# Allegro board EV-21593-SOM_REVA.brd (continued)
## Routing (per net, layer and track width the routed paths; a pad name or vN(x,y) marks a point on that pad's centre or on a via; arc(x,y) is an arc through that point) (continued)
N13: length 63.3
  TOP w0.14: v2(15.88,34.92) U7.2
  TOP w0.203: U1.P2 v1(25.82,50.14)
  L4_SIG w0.14: v1(15.62,47.37) 16.13,47.88 16.99,47.88 18.05,48.94 19.73,48.94 20.57,49.78 23.42,49.78 23.46,49.74 25.42,49.74 v1(25.82,50.14)
  L5_SIG w0.14: v2(15.88,34.92) 15.37,34.42 15.37,18.41 16.38,17.4 16.38,13.97 18.41,11.94 18.41,9.4 19.18,8.64 19.18,2.79 v1(18.03,1.65)
  BOTTOM w0.14: v1(18.03,1.65) 17.83,2.03 J2.7 ; v2(15.88,34.92) 14.86,35.94 14.86,46.61 v1(15.62,47.37)
PA_00/SPI2_MISO/OSPI_MISO/SMC0_D00: length 63.8
  TOP w0.203: v1(26.62,50.94) U1.N3
  L4_SIG w0.14: v1(24.89,9.14) 24.26,8.51 24.26,7.37 23.75,6.86 20.07,6.86 19.43,6.22 19.43,5.46 18.86,4.89 16.57,4.89 v1(16.13,4.45)
  L5_SIG w0.14: v1(24.89,9.14) 24.89,16 23.49,17.4 23.49,19.81 22.86,20.45 22.86,29.21 22.23,29.84 v2(22.23,33.02) 20.62,34.63 20.62,41.54 21.02,41.94 21.82,41.94 22.22,42.34 22.22,43.81 22.48,44.07 22.48,49.53 22.86,49.91 23.49,49.91 23.88,50.29 24.31,50.29 24.56,50.54 26.22,50.54 v1(26.62,50.94)
  BOTTOM w0.14: J2.3 16.56,4.06 v1(16.13,4.45) ; R72.2 23.49,32.38 22.86,32.38 v2(22.23,33.02)
PA_01/SPI2_MOSI/OSPI_MOSI/SMC0_D01: length 70.7
  TOP w0.14: U2.15 29.1,38.69 29.06,38.73 27.24,38.73 24.64,41.34 22.22,41.34 v1(21.82,40.94)
  TOP w0.203: U1.P3 v1(26.62,50.14)
  L4_SIG w0.14: v1(25.78,9.14) 25.02,8.38 25.02,7.24 24.13,6.35 20.32,6.35 19.81,5.84 19.81,4.32 v1(17.15,1.65)
  L5_SIG w0.14: v1(25.78,9.14) 25.78,16.51 24.51,17.78 24.51,20.19 23.37,21.34 23.37,29.47 22.87,29.97 22.87,33.66 22.48,34.04 21.98,34.04 21.22,34.8 21.22,40.34 v1(21.82,40.94) 23.02,42.14 23.02,44.36 23.42,44.76 23.42,49.23 23.93,49.74 26.22,49.74 v1(26.62,50.14)
  BOTTOM w0.14: v1(17.15,1.65) 17.19,2.16 J2.5
PA_03/SPI2_D3/OSPI_D3/TWI3_SDA/SMC0_D03: length 59.7
  TOP w0.14: v2(15.88,38.73) U8.2
  TOP w0.203: U1.R3 v1(26.62,49.34)
  L4_SIG w0.14: v1(26.62,49.34) 26.22,48.94 23.69,48.94 23.27,48.51 18.29,48.51 v1(17.15,47.37)
  L5_SIG w0.14: v1(17.15,47.37) 16.76,46.99 16.76,39.62 v2(15.88,38.73) 14.99,37.85 14.99,13.46 17.15,11.3 17.15,9.02 17.53,8.64 18.41,8.64 18.67,8.38 18.67,7.24 18.16,6.73 18.16,4.95 v1(18.67,4.45)
  BOTTOM w0.14: J2.9 18.46,4.06 v1(18.67,4.45)
PA_04/SPI2_CLK/OSPI_CLK/SMC0_D04: length 69.5
  TOP w0.14: v1(23.42,40.94) 24.82,39.54 24.82,38.68 v2(26.03,37.46)
  TOP w0.203: U1.R1 v1(25.02,49.34)
  L5_SIG w0.14: v1(19.05,1.65) 19.56,1.14 32.13,1.14 32.64,1.65 32.64,8.51 29.72,11.43 29.72,17.78 28.45,19.05 28.45,22.48 27.3,23.62 27.3,35.69 26.03,36.96 v2(26.03,37.46) ; v1(23.42,40.94) 23.42,44.12 23.82,44.52 23.82,48.96 24.2,49.34 v1(25.02,49.34)
  BOTTOM w0.14: J2.11 19.1,2.03 v1(19.05,1.65) ; R73.1 v2(26.03,37.46)
PA_05/SPI2_SEL1B/OSPI_SEL1B/SMC0_D05/SPI2_SSB: length 62.3
  TOP w0.14: U6.2 v2(15.88,31.12)
  TOP w0.203: v1(25.82,48.54) U1.T2
  L4_SIG w0.14: v1(15.62,46.61) 18.16,46.61 19.43,47.88 19.94,47.88 20.57,47.24 23.39,47.24 24.29,48.14 25.42,48.14 v1(25.82,48.54)
  L5_SIG w0.14: v2(15.88,31.12) 15.88,21.59 18.92,18.54 18.92,11.05 19.69,10.29 19.69,4.06 19.94,3.81 v1(19.94,1.65)
  BOTTOM w0.14: J2.13 19.73,2.16 v1(19.94,1.65) ; v2(15.88,31.12) 16.51,31.75 16.51,35.81 15.24,37.08 15.24,46.23 v1(15.62,46.61)
PA_10/TWI0_SCL/SPI1_CLK/TM0_TMR0/SMC0_D10: length 64.7
  TOP w0.203: v1(25.82,47.74) U1.U2
  L5_SIG w0.14: v1(25.82,47.74) 25.42,48.14 24.82,48.14 24.22,47.54 24.22,44.14 23.82,43.74 23.82,40.74 24.13,40.43 24.13,29.97 23.88,29.72 23.88,23.62 24.26,23.24 25.27,23.24 25.65,22.86 25.65,17.53 26.29,16.89 26.29,9.78 26.8,9.27 26.8,3.18 v1(25.27,1.65) 24.51,2.41 21.59,2.41 20.83,3.18 20.83,6.35 20.19,6.99 v1(20.19,8.13)
  BOTTOM w0.14: v1(25.27,1.65) 25.45,2.03 J2.31 ; v1(20.19,8.13) 19.73,7.62 J2.14
PA_12/FLG0/SPI1_MOSI/TM0_TMR1/SMC0_D12: length 68.2
  TOP w0.203: v1(29.02,46.14) U1.W6
  L4_SIG w0.14: v1(21.34,5.33) 21.84,5.84 22.35,5.84 22.61,5.59 22.61,4.06 23.24,3.43 26.16,3.43 26.67,2.92 30.1,2.92 30.48,2.54 34.67,2.54 v1(35.56,1.65)
  L5_SIG w0.14: v1(35.56,1.65) 35.56,2.92 35.43,3.05 35.43,5.84 34.8,6.48 34.8,11.18 35.31,11.68 35.31,12.32 33.91,13.72 33.91,17.15 34.67,17.91 34.67,18.67 34.04,19.3 34.04,20.95 34.67,21.59 34.67,24.64 29.97,29.34 29.97,37.78 28.96,38.8 28.96,42.54 28.62,42.88 28.62,45.74 v1(29.02,46.14)
  BOTTOM w0.14: v1(21.34,5.33) 21.34,5.38 21,5.71 J2.18
PA_15/TWI2_SDA/SPI1_D3/UART1_TXB/SMC0_D15: length 68.1
  TOP w0.14: R69.1 v1(35.42,40.14)
  TOP w0.203: v1(30.62,46.14) U1.W8
  L4_SIG w0.14: v1(30.62,46.14) 31.02,45.74 31.02,42.94 32.62,41.34 34.22,41.34 v1(35.42,40.14) ; v1(25.4,4.45) 25.91,3.94 26.92,3.94 27.43,3.43 30.61,3.43 31.12,2.92 38.23,2.92 v1(39.5,1.65)
  L5_SIG w0.14: v1(39.5,1.65) 39.5,4.57 39.81,4.89 39.81,7.3 38.99,8.13 38.99,27.69 36.7,29.97 36.7,37.33 35.42,38.61 v1(35.42,40.14)
  BOTTOM w0.14: v1(25.4,4.45) 25.45,4.83 J2.32
PB_02/MLB0_CLK/FLG3/LP1_ACK/SMC0_AWEB/TM0_ACLK4: length 128.5
  TOP w0.14: v1(11.43,43.69) 11.43,43.05 11.94,42.55 14.99,42.55 16.38,43.94 48.64,43.94 v1(50.8,41.78)
  TOP w0.203: v1(30.62,60.54) U1.B8
  L4_SIG w0.14: v2(11.3,57.4) 16.89,57.4 17.62,58.13 17.62,59.44 20.32,62.14 29.62,62.14 30.22,61.54 30.22,60.94 v1(30.62,60.54)
  L5_SIG w0.14: v2(50.67,7.37) 50.67,10.29 51.94,11.56 51.94,24 51.31,24.64 51.31,30.35 50.42,31.24 50.42,41.4 v1(50.8,41.78)
  BOTTOM w0.14: v1(50.8,41.78) 51.69,40.89 53.47,40.89 55.24,42.67 J1.96 ; J2.98 46.4,7.67 46.61,7.87 50.16,7.87 v2(50.67,7.37) ; v1(11.43,43.69) 12.83,45.09 12.83,55.88 v2(11.3,57.4)
PB_06/LP0_CLK/SPI1_SEL5B/TRACE0_CLK: length 70.9
  TOP w0.203: v1(28.22,46.94) U1.V5
  L4_SIG w0.14: v1(46.74,1.65) 45.09,3.3 32,3.3 31.37,3.94 28.32,3.94 v1(27.81,4.45)
  L5_SIG w0.14: v1(27.81,4.45) 27.18,5.08 27.18,5.97 27.43,6.22 27.43,18.03 26.42,19.05 26.42,22.86 25.53,23.75 25.53,29.34 24.64,30.23 24.64,32.1 25.4,32.86 25.4,35.56 24.89,36.07 24.89,44.57 24.62,44.84 24.62,47.14 24.82,47.34 27.82,47.34 v1(28.22,46.94)
  BOTTOM w0.14: v1(46.74,1.65) 47.04,2.16 J2.99
PB_07/LP0_D0/SPI2_SEL5B/TRACE0_D00: length 62.3
  TOP w0.14: v1(45.72,1.65) 44.83,2.54 34.92,2.54 v1(34.04,1.65)
  TOP w0.203: v1(27.42,46.14) U1.W4
  L5_SIG w0.14: v1(27.42,46.14) 27.02,45.74 27.02,43.81 26.67,43.46 26.67,38.99 28.45,37.21 28.45,23.75 29.4,22.8 29.4,22.23 32.13,19.49 32.13,10.79 33.4,9.53 33.4,4.06 34.04,3.43 v1(34.04,1.65)
  BOTTOM w0.14: J2.95 45.77,2.03 v1(45.72,1.65)
PB_08/LP0_D1/SPI1_SEL7B/TM0_TMR6/TRACE0_D01: length 61.4
  TOP w0.203: v1(26.62,46.14) U1.W3
  L4_SIG w0.14: v1(32.13,4.45) 33.02,3.56 44.7,3.56 v1(45.59,4.45)
  L5_SIG w0.14: v1(26.62,46.14) 26.22,45.74 26.22,44.74 25.27,43.79 25.27,37.08 26.67,35.69 26.67,23.37 27.43,22.61 27.43,19.05 28.57,17.91 28.57,11.43 31.75,8.26 31.75,4.83 v1(32.13,4.45)
  BOTTOM w0.14: J2.93 45.13,4.06 v1(45.59,4.45)
PB_09/LP0_D2/SPI2_SEL7B/TM0_TMR7/TRACE0_D02: length 59
  TOP w0.14: v1(44.83,1.65) 44.32,1.14 37.72,1.14 v1(37.21,1.65)
  TOP w0.203: v1(29.02,46.94) U1.V6
  L5_SIG w0.14: v1(37.21,1.65) 36.45,2.41 36.45,12.57 35.31,13.72 35.31,17.4 35.43,17.53 35.43,25.4 32.13,28.7 32.13,32.64 31.62,33.15 31.62,37.57 29.82,39.37 29.82,44.54 29.42,44.94 29.42,46.54 v1(29.02,46.94)
  BOTTOM w0.14: v1(44.83,1.65) 44.5,2.03 J2.91
PB_10/LP0_D3/SPI1_SEL2B/TRACE0_D03: length 74.5
  TOP w0.203: v1(26.62,45.34) U1.Y3
  L4_SIG w0.14: v1(22.1,5.33) 22.1,3.94 23.11,2.92 25.65,2.92 26.42,2.16 32.64,2.16 v1(33.15,1.65) 33.66,1.14 42.8,1.14 v1(43.31,1.65)
  L5_SIG w0.14: v1(33.15,1.65) 33.15,2.79 33.02,2.92 33.02,9.02 30.99,11.05 30.99,17.53 31.24,17.78 31.24,19.43 28.96,21.72 28.96,22.61 27.94,23.62 27.94,35.69 26.67,36.96 26.67,37.99 26.31,38.35 26.31,43.89 26.62,44.2 v1(26.62,45.34)
  BOTTOM w0.14: J2.22 22.27,5.71 v1(22.1,5.33) ; v1(43.31,1.65) 43.86,2.16 J2.89
PB_11/LP0_D4/SPI0_RDY/UART2_RXB/TM0_ACI2: length 70.1
  TOP w0.14: v1(23.49,7.87) 23.88,7.49 27.69,7.49 v1(28.32,8.13)
  TOP w0.203: U1.Y4 v1(27.42,45.34)
  L4_SIG w0.14: v1(28.57,5.33) 29.02,4.89 33.46,4.89 v1(33.91,4.45) 34.42,3.94 42.29,3.94 v1(42.8,4.45)
  L5_SIG w0.14: v1(33.91,4.45) 33.91,10.92 33.15,11.68 33.15,19.81 31.62,21.34 31.62,25.65 28.96,28.32 28.96,37.46 27.94,38.48 27.94,43.82 27.42,44.34 v1(27.42,45.34)
  BOTTOM w0.14: v1(23.49,7.87) 23.54,7.83 J2.26 ; J2.87 43.23,4.06 v1(42.8,4.45) ; v1(28.57,5.33) 28.62,5.71 J2.42 28.62,7.83 v1(28.32,8.13)
PB_12/LP0_D5/SPI2_SEL3B/UART2_TXB: length 66.9
  TOP w0.203: v1(29.82,46.94) U1.V7
  L4_SIG w0.14: v1(27.81,5.33) 28.32,5.84 33.4,5.84 34.35,4.89 36.51,4.89 v1(36.96,4.45)
  L5_SIG w0.14: v1(29.82,46.94) 30.22,46.54 30.22,39.62 30.23,39.62 31.88,37.97 31.88,33.78 32.64,33.02 32.64,29.21 35.81,26.03 35.81,17.53 36.32,17.02 36.32,13.33 36.83,12.83 36.83,6.86 37.46,6.22 37.46,4.95 v1(36.96,4.45) 38.61,2.79 38.61,1.65 39.12,1.14 41.91,1.14 v1(42.42,1.65)
  BOTTOM w0.14: J2.40 27.99,5.71 v1(27.81,5.33) ; v1(42.42,1.65) 42.59,2.03 J2.85
PB_13/SPI2_DQS/LP0_D6/SPI1_SEL3B/UART2_RTSB: length 75.3
  TOP w0.14: v1(34.8,1.65) 35.31,2.16 41.27,2.16 v1(41.78,1.65)
  TOP w0.203: v1(28.22,46.14) U1.W5
  L4_SIG w0.14: v1(29.21,8.13) 28.19,7.11 26.67,7.11 25.4,5.84 24.38,5.84 v1(23.88,5.33)
  L5_SIG w0.14: v1(34.8,1.65) v1(34.8,4.45) 34.29,4.95 34.29,11.3 33.53,12.06 33.53,17.27 34.29,18.03 34.29,18.54 33.66,19.18 33.66,20.07 32.64,21.08 32.64,25.53 29.46,28.7 29.46,37.64 28.32,38.78 28.32,44.33 27.82,44.83 27.82,45.74 v1(28.22,46.14)
  BOTTOM w0.14: J2.83 41.96,2.03 v1(41.78,1.65) ; v1(29.21,8.13) 29.21,6.69 J2.44 29.26,5.16 29.53,4.89 34.35,4.89 v1(34.8,4.45) ; J2.27 24.18,4.19 23.88,4.49 v1(23.88,5.33)
PB_14/LP0_D7/SPI0_SEL3B/UART2_CTSB: length 64.2
  TOP w0.203: v1(36.22,45.34) U1.Y14
  L5_SIG w0.14: v1(41.02,1.65) 41.02,3.49 41.08,3.56 41.08,6.22 41.02,6.29 41.02,27.18 37.46,30.73 37.46,39.03 36.62,39.88 36.62,41.94 36.22,42.34 v1(36.22,45.34) ; v1(29.72,5.33) 29.72,3.68 30.35,3.05 v1(30.35,1.65)
  BOTTOM w0.14: J2.46 29.89,5.84 v1(29.72,5.33) ; v1(30.35,1.65) 30.86,1.14 40.51,1.14 v1(41.02,1.65) 41.32,2.16 J2.81
PB_15/LP1_D0/SPI0_SEL4B/SMC0_ADDR4: length 51.6
  TOP w0.14: v1(40,4.45) 40.45,4.89 45.15,4.89 v1(45.59,5.33)
  TOP w0.203: v1(36.22,46.14) U1.W14
  L5_SIG w0.14: v1(36.22,46.14) 35.82,45.74 35.82,38.99 37.08,37.73 37.08,30.48 40,27.56 40,7.75 40.13,7.62 40.13,4.7 v1(40,4.45)
  BOTTOM w0.14: J2.96 45.77,5.71 v1(45.59,5.33)
PC_00/LP1_D1/TWI4_SCL/TRACE0_D04/SPI1_SEL4B: length 53.1
  TOP w0.203: v1(35.42,46.94) U1.V13
  L4_SIG w0.14: v1(38.99,4.45) 39.43,4.89 44.45,4.89 v1(44.83,5.33)
  L5_SIG w0.14: v1(38.99,4.45) 39.5,4.95 39.5,6.99 38.61,7.87 38.61,26.8 35.18,30.23 35.18,36.83 34.92,37.08 34.92,43.97 35.02,44.07 35.02,46.54 v1(35.42,46.94)
  BOTTOM w0.14: v1(44.83,5.33) 45.13,5.71 J2.94
PC_01/LP1_D2/TWI4_SDA/TRACE0_D05/SPI2_SEL4B: length 51.7
  TOP w0.203: v1(37.02,46.14) U1.W15
  L5_SIG w0.14: v1(44.83,4.45) 43.94,3.56 41.97,3.56 41.47,4.06 41.47,6.35 42.04,6.92 42.04,20.07 41.4,20.7 41.4,27.5 37.85,31.05 37.85,39.58 37.42,40 37.42,41.54 36.62,42.34 36.62,45.74 v1(37.02,46.14)
  BOTTOM w0.14: v1(44.83,4.45) 44.32,4.95 44.32,5.46 44.5,5.71 J2.92
PC_02/LP1_D3/TWI5_SCL/TRACE0_D06/SPI1_SEL6B: length 46.9
  TOP w0.203: v1(37.02,45.34) U1.Y15
  L5_SIG w0.14: v1(37.02,45.34) 37.02,44.34 37.82,43.54 37.82,40.26 38.23,39.85 38.23,31.35 38.6,30.98 41.15,28.45 41.78,27.81 41.78,21.15 42.35,20.57 42.35,5.08 42.55,4.89 43.18,4.89 v1(43.56,4.45)
  BOTTOM w0.14: v1(43.56,4.45) 43.86,4.83 J2.90
PC_03/LP1_D4/TWI5_SDA/TRACE0_D07/SPI2_SEL6B: length 45.4
  TOP w0.203: v1(37.82,46.14) U1.W16
  L5_SIG w0.14: v1(43.43,5.33) 43.43,6.1 42.67,6.86 42.67,20.83 42.16,21.34 42.16,27.94 38.6,31.5 38.6,40.13 38.22,40.51 38.22,43.54 37.42,44.34 37.42,45.74 v1(37.82,46.14)
  BOTTOM w0.14: J2.88 43.23,5.71 v1(43.43,5.33)
PC_04/LP1_D5/OSPI_SEL2B/SMC0_ADDR5: length 49.2
  TOP w0.203: v1(38.62,45.34) U1.Y17
  L4_SIG w0.14: v1(42.8,5.33) 43.31,5.84 45.85,5.84 v1(46.35,5.33)
  L5_SIG w0.14: v1(38.62,45.34) 39.42,44.54 39.42,31.62 43.18,27.86 43.18,25.53 43.81,24.89 43.81,14.48 44.07,14.22 44.07,7.62 v1(46.35,5.33)
  BOTTOM w0.14: v1(42.8,5.33) 42.59,5.71 J2.86
PC_05/LP1_D6/OSPI_SEL3B/TM0_TMR8/SMC0_ADDR6: length 51.3
  TOP w0.203: v1(36.22,46.94) U1.V14
  L4_SIG w0.14: v1(41.91,5.33) 41.4,5.84 39.5,5.84 v1(38.99,5.33)
  L5_SIG w0.14: v1(38.99,5.33) 38.99,6.86 38.23,7.62 38.23,26.29 34.67,29.84 34.67,42.35 34.22,42.8 34.22,47.14 34.42,47.34 U1.V14 v1(36.22,46.94)
  BOTTOM w0.14: J2.84 41.96,5.71 v1(41.91,5.33)
PC_06/LP1_D7/SPI1_RDY/SMC0_ADDR7: length 49.9
  TOP w0.203: v1(38.62,46.14) U1.W17
  L5_SIG w0.14: v1(42.04,4.45) 42.55,3.94 43.69,3.94 44.07,4.32 44.07,6.22 43.05,7.24 43.05,21.08 42.55,21.59 42.55,28.07 41.66,28.96 39.02,31.62 39.02,43.94 38.22,44.74 38.22,45.74 v1(38.62,46.14)
  BOTTOM w0.14: v1(42.04,4.45) 42.04,4.49 41.32,5.21 J2.82
PC_07/LP1_CLK/OSPI_SEL4B/TM0_TMR9/SYS_FAULT: length 46.1
  TOP w0.203: v1(39.42,45.34) U1.Y18
  L5_SIG w0.14: v1(47.37,5.33) 44.45,8.26 44.45,21.84 45.09,22.48 45.09,24.64 44.7,25.02 44.32,25.02 43.56,25.78 43.56,28.04 43.55,28.05 39.82,31.75 39.82,44.94 v1(39.42,45.34)
  BOTTOM w0.14: J2.100 47.04,5.71 v1(47.37,5.33)
PG1: length 34.5
  TOP w0.254: v2(47.12,14.22) 46.71,14.45 46.48,14.67 U14.2 ; U15.1 19.31,13.99 19.56,13.74 19.56,13.08 19.81,12.83 20.7,12.83 R56.2
  TOP w0.305: R56.2 v2(20.83,12.06)
  L4_SIG w0.305: v2(47.12,14.22) 47.12,12.95 46.35,12.19 44.07,12.19 42.42,10.54 34.42,10.54 33.53,9.65 29.97,9.65 27.56,12.06 v2(20.83,12.06)
PG3: length 15.3
  TOP w0.254: U5.1 33.66,15.64 33.66,14.99 33.91,14.73 v2(34.8,14.73) ; v2(43.56,13.46) 44.58,13.46 44.84,13.72 U14.11
  TOP w0.305: R62.1 42.93,13.21 43.18,13.46 v2(43.56,13.46)
  L4_SIG w0.305: v2(43.56,13.46) 43.56,14.48 42.93,15.11 36.45,15.11 36.07,14.73 v2(34.8,14.73)
PG4: length 2.2
  TOP w0.254: U5.14 30.1,15.64 29.46,14.99 R61.1
RXD: length 15
  TOP w0.14: v2(20.19,74.8) 19.3,75.14 U11.8 ; v2(19.81,85.47) 19.43,85.11 U10.2
  L4_SIG w0.14: v2(19.81,85.47) 19.18,84.84 19.18,75.82 v2(20.19,74.8)
SPIFLASH_SPI2D2: length 17.1
  TOP w0.14: U2.9 29.09,31.09 26.64,31.09 v2(26.03,30.48) ; v2(15.88,33.53) 16.62,34.28 U7.4
  L4_SIG w0.14: v2(26.03,30.48) 25.4,31.12 20.83,31.12 18.41,33.53 v2(15.88,33.53)
  BOTTOM w0.14: R79.2 v2(26.03,30.48)
SPIFLASH_SPI2D3: length 9.4
  TOP w0.14: v2(23.49,40) 22.86,39.37 21.72,39.37 21.08,40 U2.1 19.05,40 18.8,39.75 18.8,38.99 18.54,38.73 17.4,38.73 17.27,38.61 17.27,38.09 U8.4
  BOTTOM w0.14: v2(23.49,40) R78.2
SYS_BMODE0: length 45.3
  TOP w0.14: v2(8.26,80.9) SW1.1
  TOP w0.203: U1.B10 v1(32.22,60.54)
  L4_SIG w0.14: v2(8.26,80.9) 8.26,70.74 9.14,69.85 18.54,69.85 20.32,68.07 30.1,68.07 30.86,67.31 30.86,63.75 32.22,62.4 v1(32.22,60.54)
  BOTTOM w0.14: v2(8.26,80.9) 8.26,79.69 R20.1
SYS_BMODE1: length 59.4
  TOP w0.14: v2(3.05,68.96) 3.05,67.03 SW1.2
  TOP w0.203: v1(31.42,60.54) U1.B9
  L4_SIG w0.14: v1(31.42,60.54) 31.42,62.18 29.84,63.75 29.84,66.8 29.08,67.56 20.07,67.56 18.29,69.34 7.11,69.34 5.97,70.48 5.97,77.72 6.99,78.74 v2(6.99,80.9)
  BOTTOM w0.14: v2(3.05,68.96) 3.05,69.85 R21.1 3.02,74.45 5.05,76.48 5.05,78.97 v2(6.99,80.9)
SYS_BMODE2: length 47.1
  TOP w0.14: v2(3.18,80.9) SW1.4
  TOP w0.203: U1.A8 v1(30.62,61.34)
  L4_SIG w0.14: v2(3.18,80.9) 3.94,80.14 3.94,70.1 5.21,68.83 18.03,68.83 19.81,67.06 28.03,67.06 28.79,66.29 28.79,63.79 30.62,61.96 v1(30.62,61.34)
  BOTTOM w0.14: v2(3.18,80.9) 3.18,79.69 R22.1
SYS_CLKIN0: length 38
  TOP w0.14: v2(44.45,39.37) 44.45,39.19 44.48,38.58 R23.2 ; R33.2 20.19,52.07 20.45,52.32 23.17,52.32 23.75,51.74 v1(25.02,51.74)
  TOP w0.203: U1.N1 v1(25.02,51.74)
  L5_SIG w0.14: v1(25.02,51.74) U1.N1 43.05,51.34 44.45,49.94 v2(44.45,39.37)
SYS_CLKOUT: length 44
  TOP w0.203: v1(26.62,51.74) U1.M3
  L4_SIG w0.14: v1(26.62,51.74) 26.22,52.14 23.62,52.14 23.42,52.34 6.49,52.34 v2(6.48,52.32)
  L5_SIG w0.14: v2(6.48,52.32) 6.48,48.89 3.68,46.1 3.68,34.29 v1(5.46,32.51)
  BOTTOM w0.14: v1(5.46,32.51) J3.38
SYS_XTAL0: length 6.3
  TOP w0.14: U1.L1 24.38,52.94 23.73,53.59 20.32,53.59 20.07,53.34 R32.1
TWI2_SCL: length 179.1
  TOP w0.14: v1(48.89,3.43) 32.51,3.43 31.62,2.54 28.7,2.54 v1(27.81,1.65) ; v2(44.32,88.9) R112.2 ; v2(46.99,30.48) 46.35,31.37 46.33,31.38 U9.12 ; U16.8 16.81,65.79 17.19,66.17 17.4,66.17 v2(18.29,67.06) ; v1(33.82,37.34) R70.2
  L4_SIG w0.14: v1(33.82,37.34) 28.57,37.34 27.94,36.7 12.95,36.7 12.7,36.96 12.7,37.72 v2(12.06,38.35)
  L5_SIG w0.14: v2(44.32,88.9) 43.31,89.92 40.77,89.92 39.88,89.03 29.59,89.03 28.19,87.63 22.23,87.63 21.34,86.74 21.34,73.91 18.29,70.87 v2(18.29,67.06) ; v2(46.99,30.48) 46.99,27.43 51.18,23.24 51.18,12.57 48.89,10.29 v1(48.89,3.43)
  BOTTOM w0.14: v2(12.06,38.35) 12.57,37.85 13.72,37.85 14.48,38.61 14.48,53.98 13.84,54.61 13.84,59.05 15.62,60.83 15.62,65.15 16.26,65.79 17.02,65.79 v2(18.29,67.06) ; R70.2 v1(33.82,37.34) 41.44,29.72 46.23,29.72 v2(46.99,30.48) ; J2.39 27.99,2.03 v1(27.81,1.65)
TWI2_SDA: length 183.4
  TOP w0.14: U9.19 46.33,36.81 v2(46.35,36.83) ; v1(28.7,1.65) 29.19,2.14 32.64,2.14 33.42,2.92 49.53,2.92 v1(50.04,3.43) ; R69.2 v1(35.43,37.34) ; v2(45.59,88.9) R113.2 ; U16.9 16.16,66.17 16.54,66.55 16.76,66.55 v2(17.27,67.06)
  L4_SIG w0.14: v2(46.35,36.83) 45.85,37.34 v1(35.43,37.34) 34.92,37.85 29.97,37.85 29.46,38.35 19.69,38.35 18.54,37.21 14.48,37.21 v2(13.33,38.35)
  L5_SIG w0.14: v2(46.35,36.83) 46.99,37.46 49.28,37.46 49.91,36.83 49.91,25.27 51.56,23.62 51.56,11.94 50.04,10.41 v1(50.04,3.43) ; v2(17.27,67.06) 17.27,70.74 20.83,74.3 20.83,87 21.84,88.01 27.94,88.01 29.34,89.41 39.5,89.41 40.39,90.3 44.2,90.3 v2(45.59,88.9)
  BOTTOM w0.14: R69.2 v1(35.43,37.34) ; v2(17.27,67.06) 16.51,66.29 14.73,66.29 14.1,65.66 14.1,60.45 13.33,59.69 13.33,54.36 14.1,53.59 14.1,39.12 v2(13.33,38.35) ; v1(28.7,1.65) 28.62,2.16 J2.41
TXD: length 9.2
  TOP w0.14: U10.30 16.63,83.19 v2(16.38,82.68) ; U11.11 v2(16.89,77.09)
  L5_SIG w0.14: v2(16.38,82.68) 17.65,81.41 17.65,77.85 v2(16.89,77.09)
USB_SHELL: length 20.8
  BOTTOM w0.508: C192.1 7.62,96.45
  BOTTOM w0.635: 10.79,96.45 7.62,96.45 R82.1
  BOTTOM w0.889: P2.6 17.15,96.45 17.15,99.45 ; 10.79,99.45 17.15,99.45 ; 10.79,99.45 P2.9 ; 10.79,99.45 10.79,96.45 P2.7 ; 17.15,99.45 P2.8
USB_VBUS: length 10
  TOP w0.305: v2(18.8,94.49) 18.23,94.49 17.4,93.66 D1.1 16.26,93.66 16.26,95.08 15.96,95.38 15.52,95.38 15.27,95.63 P2.1
  BOTTOM w0.305: FER1.1 17.15,94.49 v2(18.8,94.49) 19.43,94.49 19.69,94.23 C191.1
VTT: length 94.8
  TOP w0.254: 58.74,72.99 U12.5 ; U12.3 58.74,71.99 C4.1
  TOP w0.305: C17.1 57.79,77.98 v2(57.53,77.72) ; C2.1 56.39,77.34 v2(56.77,77.72)
  TOP w0.406: 57.73,72.91 57.76,72.99 ; 57.73,72.91 57.53,72.99 v2(57.53,73.91) v2(57.53,74.68) v2(57.53,75.44) 57.53,75.49 v2(58.29,74.68) v2(59.05,74.68) ; 57.73,72.91 57.74,72.99 ; C4.1 58.74,72.99 ; v2(57.53,76.2) v2(57.53,76.96) 57.53,77.41
  BOTTOM w0.203: 34.57,86.54 33.56,86.54 RN7.7 ; RN7.8 34.06,86.22 34.07,86.23
  BOTTOM w0.254: 36.27,66.74 36.77,66.74 ; 36.27,66.74 34.57,66.74 RN6.5 ; 36.27,66.74 RN5.8 ; 36.77,66.74 RN5.7 ; 36.77,66.74 37.27,66.74 RN5.6 ; 44.02,74.49 45.09,74.55 45.09,76.07 45.21,76.19 ; 44.02,74.49 45.21,74.49 45.21,76.19 ; 44.02,74.49 44.02,73.99 ; 44.02,74.49 RN2.5 ; RN6.6 34.07,66.74 33.57,66.74 ; RN1.5 45.09,77.69 45.09,79.39 44.02,79.89 ; RN3.6 44.02,80.39 ; 44.02,79.89 44.02,79.39 RN3.8 ; 44.02,79.89 44.02,80.39 ; 44.02,79.89 RN3.7 ; RN1.8 44.02,76.19 44.02,76.69 ; 37.27,86.34 RN4.7 ; 37.27,86.34 36.77,86.34 ; 37.27,86.34 37.77,86.34 ; 44.02,80.39 44.02,80.89 RN3.5 ; 40.26,86.59 40.25,86.59 40,86.34 37.77,86.34 ; 44.02,72.99 RN2.8 ; 44.02,72.99 44.02,73.49 ; 44.02,72.99 45.09,72.99 ; 44.02,72.99 45.09,73.03 45.09,72.99 ; 33.57,66.74 RN6.7 ; 33.57,66.74 33.07,66.74 RN6.8 ; RN1.6 44.02,77.19 ; 45.09,72.99 45.09,68.52 44.02,68.34 42.42,66.74 37.77,66.74 RN5.5 ; 44.02,77.19 44.02,76.69 ; 44.02,77.19 44.02,77.69 ; 36.27,86.34 RN4.5 ; 36.27,86.34 36.77,86.34 ; 36.27,86.34 34.57,86.34 ; RN2.7 44.02,73.49 ; RN1.7 44.02,76.69 ; 44.02,73.49 44.02,73.99 ; 44.02,73.99 RN2.6 ; RN4.6 36.77,86.34 ; 37.77,86.34 RN4.8 ; 44.02,76.69 45.21,76.19 ; 34.57,86.54 34.57,86.34 ; 34.57,86.34 34.07,86.34
  BOTTOM w0.305: v2(57.73,72.95) 57.73,74.11 v2(58.29,74.68) ; v2(59.05,74.68) v2(59.05,73.91) ; 46.12,68.58 47.62,68.58 C18.1 C20.1 ; v2(40.26,87.63) 40.26,86.59 C19.1 41.27,86.59 v2(41.27,87.63) ; 44.02,80.89 44.45,80.89 ; 45.09,68.58 44.08,68.58 45.09,68.52 ; 42.29,87.5 42.16,87.63 v2(42.29,87.63) ; 41.78,66.43 41.78,66.74
  vias: v2(56.77,76.96) v2(56.77,76.96) v2(56.77,76.96) v2(56.77,76.96) v2(56.77,76.2) v2(56.77,76.2) v2(56.77,76.2) v2(56.77,76.2) v2(56.77,75.44) v2(56.77,75.44) v2(56.77,75.44) v2(56.77,75.44) v2(56.77,74.68) v2(56.77,74.68) v2(56.77,73.91) v2(56.77,73.91) v2(57.73,72.19) v2(58.29,77.72) v2(58.29,77.72) v2(58.29,76.96) v2(58.29,76.96) v2(58.29,76.2) v2(58.29,76.2) v2(58.29,75.44) v2(58.29,75.44) v2(58.29,73.91) v2(58.29,73.91) v2(59.05,77.72) v2(59.05,76.96) v2(59.05,76.2) v2(59.05,75.44)
~CON_RESET_IN: length 80.3
  TOP w0.14: v2(51.82,34.67) 51.82,36.83 52.2,37.21 54.74,37.21 54.99,37.46 54.99,38.1 R51.2 55.75,38.1 56.39,38.73 U18.2
  L4_SIG w0.14: v2(10.79,36.32) 11.68,35.43 14.73,35.43 15.49,36.2 18.67,36.2 21.08,33.78 29.59,33.78 30.86,32.51 40.89,32.51 43.56,35.18 51.31,35.18 v2(51.82,34.67)
  L5_SIG w0.14: v2(10.79,36.32) 10.16,35.69 10.16,30.73 12.95,27.94 12.95,24.26 9.65,20.95 9.65,15.24 v1(8.76,14.35)
  BOTTOM w0.14: J3.96 8.26,14.1 v1(8.76,14.35)
~CTS: length 21.5
  TOP w0.14: U11.3 11.43,77.74 v2(11.05,77.47) ; v2(19.81,88.14) 19.78,88.11 U10.8
  L5_SIG w0.14: v2(19.81,88.14) 18.67,87 13.97,87 13.08,86.11 13.08,79.5 v2(11.05,77.47)
  BOTTOM w0.14: v2(11.05,77.47) 11.43,77.85 12.19,77.85 R86.2
~DMC0_CAS: length 41.2
  TOP w0.203: U1.E20 v1(40.22,57.34) ; v1(33.82,74.34) U13.K3
  L5_SIG w0.14: v1(40.22,57.34) 39.82,57.74 38.42,57.74 38.22,57.54 38.22,57.14 38.02,56.94 35.22,56.94 35.02,56.74 35.02,56.24 34.82,56.04 34.42,56.04 34.22,56.24 34.22,57.54 34.02,57.74 33.52,57.74 33.32,57.54 33.32,57.24 33.12,57.04 32.82,57.04 32.62,57.24 32.62,66.74 33.02,67.14 33.02,72.94 33.42,73.34 33.42,74.54 33.22,74.74 33.22,75.44 33.42,75.64 33.62,75.64 33.82,75.44 v1(33.82,74.34)
  BOTTOM w0.14: v1(33.82,74.34) 34.22,73.94 34.22,72.14 34.42,71.94 35.22,71.94 35.42,71.74 35.42,71.54 35.02,71.14 35.02,70.94 35.42,70.54 35.42,69.49 35.22,69.29 35.02,69.29 34.77,69.54 34.22,69.54 34.07,69.39 RN6.3
~DMC0_CK: length 33.7
  TOP w0.203: U1.J19 v1(40.22,54.94) ; v1(33.82,78.34) U13.K7
  L4_SIG w0.076: v1(33.82,78.34) 33.78,77.98 33.78,77.72 33.66,77.6 33.53,77.6 33.4,77.72 33.26,77.72 33.15,77.61 33.15,74.97 33.42,74.7 33.42,73.19 33.15,72.92 33.15,68.74 32.82,68.41 32.82,67.14 33.15,66.81 33.15,57.41 34.42,56.14 34.91,56.14 35.31,55.74 35.31,54.99 35.43,54.86 35.69,54.86 35.81,54.99 35.81,55.26 35.9,55.34 40.21,55.34 40.31,55.24 40.31,55.17 v1(40.22,54.94)
  BOTTOM w0.14: v1(33.82,78.34) 33.82,77.34 R16.2
~DMC0_CS0: length 41.3
  TOP w0.203: U1.F20 v1(41.02,57.34) ; v1(34.62,73.54) U13.L2
  L5_SIG w0.14: v1(41.02,57.34) 41.62,57.34 41.82,57.54 41.82,57.94 41.62,58.14 40.82,58.14 40.62,58.34 40.62,59.14 40.42,59.34 35.22,59.34 35.02,59.54 35.02,61.54 34.82,61.74 34.42,61.74 34.22,61.94 34.22,67.74 34.42,67.94 35.42,67.94 35.62,67.74 36.02,67.74 36.22,67.94 36.22,68.14 36.02,68.34 34.42,68.34 34.22,68.54 34.22,68.74 34.42,68.94 34.82,68.94 35.02,68.74 36.02,68.74 36.22,68.94 36.22,70.94 36.02,71.14 34.42,71.14 34.22,71.34 34.22,71.94 34.62,72.34 v1(34.62,73.54)
  BOTTOM w0.14: v1(34.62,73.54) 34.62,72.54 34.82,72.34 35.42,72.34 35.82,71.94 35.82,69.14 35.42,68.74 35.42,68.54 35.62,68.34 35.62,67.94 35.42,67.74 35.22,67.74 35.02,67.94 35.02,68.34 34.82,68.54 34.57,68.54 RN6.4
~DMC0_LDQS: length 33.2
  TOP w0.203: v1(25.02,57.34) U1.F1 ; U13.G3 v1(31.42,74.34)
  L5_SIG w0.076: v1(25.02,57.34) 25.42,57.74 26.82,57.74 27.02,57.94 27.02,61.74 27.3,62.03 27.3,66.29 25.91,67.69 25.91,69.72 26.16,69.98 27.18,69.98 27.3,70.1 27.3,70.36 27.18,70.48 26.16,70.48 25.91,70.74 25.91,71.25 26.16,71.5 27.43,71.5 27.56,71.63 27.56,71.88 27.43,72.01 26.16,72.01 25.91,72.26 25.91,75.31 26.16,75.57 27.18,75.57 27.3,75.44 27.94,75.44 28.07,75.57 30.86,75.57 31.12,75.31 31.12,75.06 31.37,74.42 v1(31.42,74.34)
~DMC0_RAS: length 41.3
  TOP w0.203: U1.F19 v1(39.42,57.34) ; v1(33.02,74.34) U13.J3
  L5_SIG w0.14: v1(39.42,57.34) 39.02,56.94 39.02,55.54 38.82,55.34 38.42,55.34 38.22,55.54 38.22,55.94 38.02,56.14 37.62,56.14 37.42,55.94 37.42,55.54 37.22,55.34 36.82,55.34 36.62,55.54 36.62,55.94 36.42,56.14 35.92,56.14 35.72,55.94 35.72,55.54 35.52,55.34 33.62,55.34 33.42,55.54 33.42,56.44 33.22,56.64 32.72,56.64 32.62,56.54 32.62,56.34 32.42,56.14 32.02,56.14 31.82,56.34 31.82,66.74 32.62,67.54 32.62,73.94 v1(33.02,74.34)
  BOTTOM w0.14: v1(33.02,74.34) 33.02,75.34 33.22,75.54 33.42,75.54 33.62,75.34 33.62,74.94 U13.J3 33.42,73.34 33.02,72.94 33.02,69.39 33.07,69.34 RN6.1
~DMC0_RESET: length 31.6
  TOP w0.14: U1.B12 33.82,60.54 33.82,61.54 34.42,62.14 34.42,66.17 34.93,66.68 42.36,66.68 43.22,67.53 v1(43.22,71.37) ; R6.2 39.22,71.94 39.62,72.34 39.62,73.34 U13.T2
  TOP w0.203: U13.T2 v1(38.62,73.54)
  BOTTOM w0.14: 42.42,71.63 42.22,71.34 39.22,71.34 39.02,71.54 39.02,73.14 v1(38.62,73.54) ; 42.42,71.63 42.67,71.37 v1(43.22,71.37) ; 42.42,71.63 42.42,72.54 42.22,72.74 42.22,72.99 RN2.1
~DMC0_UDQS: length 33.4
  TOP w0.203: U13.B7 v1(27.42,78.34) ; v1(27.42,61.34) U1.A4
  BOTTOM w0.089: v1(27.42,61.34) 27.42,62.28 27.71,62.57 27.71,68.71 27.29,69.13 27.29,72.07 27.02,72.34 27.02,74.85 27.29,75.13 27.29,75.41 27.15,75.55 26.45,75.55 26.03,75.13 24.22,75.13 23.94,75.41 23.94,76.11 23.8,76.25 23.52,76.25 23.38,76.11 23.38,75.41 23.1,75.13 22.4,75.13 22.12,75.41 22.12,77.09 22.4,77.37 24.78,77.37 25.48,76.67 27.43,76.67 28.27,77.51 28.27,77.74 28.13,77.88 27.99,77.88 27.76,77.65 27.57,77.65 27.42,77.8 v1(27.42,78.34)
~DMC0_WE: length 41.3
  TOP w0.203: U1.A12 v1(34.62,61.34) ; v1(34.62,74.34) U13.L3
  L5_SIG w0.14: v1(34.62,61.34) U1.A12 34.22,59.54 34.02,59.34 33.62,59.34 33.42,59.54 33.42,65.94 33.82,66.34 33.82,69.14 34.02,69.34 35.02,69.34 35.22,69.14 35.62,69.14 35.82,69.34 35.82,69.54 35.62,69.74 34.02,69.74 33.82,69.94 33.82,70.14 34.02,70.34 34.82,70.34 35.02,70.14 35.62,70.14 35.82,70.34 35.82,70.54 35.62,70.74 34.02,70.74 33.82,70.94 33.82,72.14 34.22,72.54 34.22,75.34 34.42,75.54 36.02,75.54 36.22,75.34 36.22,75.14 36.02,74.94 35.42,74.94 35.22,75.14 34.82,75.14 34.62,74.94 v1(34.62,74.34)
  BOTTOM w0.14: v1(34.62,74.34) 37.47,77.19 RN1.3
~JTG0_TRST: length 82.5
  TOP w0.14: v1(19.05,65.15) 19.56,65.74 23.49,65.74 24.23,65 28.56,65 U1.A10 ; 3.81,48.89 3.81,48.01 4.19,47.62 R92.2 R93.1
  L4_SIG w0.14: v1(19.05,65.15) 10.67,65.15 9.4,63.88 v2(1.4,63.88)
  L5_SIG w0.14: v1(5.46,26.92) 3.18,29.21 3.18,46.74 3.81,47.37 3.81,48.89 2.67,50.04 2.67,57.15 3.18,57.66 3.18,62.1 v2(1.4,63.88)
  BOTTOM w0.14: J3.56 5.84,26.8 v1(5.46,26.92)
~RTS: length 16.1
  TOP w0.14: v2(17.4,82.68) 17.63,83.19 U10.32 ; U11.6 11.43,75.79 v2(11.05,76.07)
  L5_SIG w0.14: v2(17.4,82.68) 16.64,83.44 14.48,83.44 13.59,82.55 13.59,78.61 v2(11.05,76.07)
  BOTTOM w0.14: v2(11.05,76.07) 11.56,76.3 R87.2
~SP2IFLASH_CS_EN: length 36.9
  TOP w0.14: v2(13.97,32.38) 14.59,31.76 U6.1 ; U16.20 10.26,61.31 v2(9.65,60.71)
  BOTTOM w0.14: v2(13.97,32.38) R81.1 R75.2 11.18,31.6 9.91,32.87 9.91,59.05 9.65,59.31 v2(9.65,60.71)
~SPI2D2_D3_EN: length 38.6
  TOP w0.14: v2(13.33,39.37) 13.96,39.38 U8.1 ; v2(13.33,36.07) 13.96,35.57 U7.1 ; U16.21 11.3,60.66 v2(10.79,60.71)
  L4_SIG w0.14: v2(10.79,60.71) 12.06,60.71 12.83,59.94 15.88,59.94 16.51,59.31 v2(16.51,58.29)
  L5_SIG w0.14: v2(13.33,36.07) 13.33,36.2 12.67,36.86 12.67,38.73 13.31,39.37 v2(13.33,39.37) 14.73,40.77 14.73,56.52 v2(16.51,58.29)
  BOTTOM w0.14: R76.2 R74.1 12.06,35.81 12.32,36.07 v2(13.33,36.07)
~SPIFLASH_CS: length 9.1
  TOP w0.14: U6.4 17.15,30.47 17.15,30.99 17.27,31.12 18.54,31.12 18.8,31.37 18.8,32.13 19.05,32.38 U2.7 22.86,32.38 v2(23.49,33.02)
  BOTTOM w0.14: v2(23.49,33.02) R77.2
~SYS_FAULT: length 15
  TOP w0.14: R9.2 R10.2 24,66.34 24.77,65.58 28.78,65.58 U1.A11
~SYS_HWRST: length 148.5
  TOP w0.14: U16.14 12.91,66.21 12.32,66.8 v2(11.43,66.8) ; U1.A9 31.78,60.98 31.77,60.98 28.37,64.39 v1(23.02,64.39) 22.35,64.39 R12.1 ; v2(50.67,29.84) R46.2 ; v2(26.03,29.21) 25.4,29.84 25.4,36.32 24.89,36.83 21.72,36.83 21.08,37.46 U2.3 19.05,37.46 18.29,36.7 12.95,36.7 12.57,36.32 12.57,35.75 12.19,35.37 10.31,35.37 10.06,35.62 10.06,36.58 9.81,36.83 v2(9.27,36.83) ; v1(55.12,23.75) 57.15,23.75 U4.2 57.42,23.11 57.79,22.75 R48.2
  L4_SIG w0.14: v2(26.03,29.21) 27.81,29.21 28.07,28.96 34.54,28.96 35.43,29.84 v2(50.67,29.84) 52.45,29.84 54.61,27.69 54.61,24.26 v1(55.12,23.75) ; v1(23.02,64.39) 21.62,65.79 12.45,65.79 v2(11.43,66.8)
  L5_SIG w0.14: v2(11.43,66.8) 12.57,65.66 12.57,43.94 8.51,39.88 8.51,37.59 v2(9.27,36.83) 8.51,36.07 8.51,34.29 9.14,33.66 9.14,25.53 8.76,25.15 v2(8.76,15.24)
  BOTTOM w0.14: v2(8.76,15.24) 8.26,14.73 J3.94
~SYS_RESOUT: length 18.6
  TOP w0.14: R11.2 22.3,62.33 22.49,62.14 23.22,62.14 23.42,61.94 23.42,57.14 v1(23.82,56.74)
  TOP w0.203: v1(32.22,59.74) U1.C10
  L4_SIG w0.14: v1(23.82,56.74) 23.82,57.34 24.22,57.74 31.62,57.74 31.82,57.94 31.82,59.34 v1(32.22,59.74)
~TARGET_RESET: length 106
  TOP w0.14: R94.2 v2(10.79,48.89) ; U18.1 56.13,39.68 55.82,39.37 R50.2 55.09,39.4 54.48,40 51.05,40 v2(49.15,38.1) ; v1(8.51,26.16) 7.11,24.77 4.06,24.77 2.03,26.8 2.03,44.83 v2(1.52,45.34)
  L4_SIG w0.14: v2(10.79,48.89) 9.65,47.75 3.94,47.75 v2(1.52,45.34) ; v2(49.15,38.1) 49.78,37.46 49.78,36.58 49.15,35.94 42.42,35.94 42.16,36.2 40,36.2 39.12,35.31 34.92,35.31 34.29,35.94 v2(22.23,35.94)
  BOTTOM w0.14: J3.58 8.51,26.16 v1(8.51,26.16) 8.51,24.77 9.14,24.13 20.45,24.13 21.08,24.77 21.08,35.56 21.46,35.94 v2(22.23,35.94)
~UART0_EN: length 29.8
  TOP w0.14: U11.13 19.3,78.39 19.56,78.13 19.56,76.69 19.3,76.44 U11.10 17.15,76.44 16.78,76.58 v2(16,76.58) ; v2(11.3,59.69) 12.88,59.69 U16.22
  L5_SIG w0.14: v2(16,76.58) 16,75.06 15.37,74.42 15.37,72.39 14.6,71.63 14.6,70.61 13.97,69.98 11.43,69.98 10.79,69.34 10.79,65.79 11.3,65.28 v2(11.3,59.69)
  BOTTOM w0.14: v2(16,76.58) R88.1
~UART0_FLOW_EN: length 34.4
  TOP w0.14: U11.1 13.67,79.04 v2(14.73,77.98) 13.84,77.09 U11.4 ; U16.23 13.56,58.93 13.31,58.67 v2(11.3,58.67)
  L5_SIG w0.14: v2(14.73,77.98) 15.37,77.34 15.37,75.95 14.1,74.68 14.1,72.9 13.46,72.26 10.79,72.26 9.02,70.48 9.02,60.07 10.41,58.67 v2(11.3,58.67)
  BOTTOM w0.14: v2(14.73,77.98) R89.1
$3N3239: length 23.4
  TOP w0.203: U1.J4 v1(27.42,54.94) ; v1(41.02,56.54) U1.G20
  L4_SIG w0.14: v1(27.42,54.94) 27.82,55.34 31.62,55.34 31.82,55.14 31.82,53.94 32.02,53.74 34.22,53.74 34.62,53.34
  L4_SIG w0.406: v1(41.02,56.54) 41.49,56.54 41.91,56.12 41.91,54.12 41.13,53.34 34.62,53.34
  BOTTOM w0.406: v1(41.02,56.54) 41.83,56.54
  BOTTOM w0.508: 41.83,56.54 R2.2
$3N3333: length 2.9
  TOP w0.14: R5.1 34.62,79.14 U13.L8
$3N3334: length 40.6
  TOP w0.203: v1(35.42,79.14) U13.M8 ; v1(32.22,72.74) U13.H1
  TOP w0.406: v1(32.22,72.74) C11.2 33.73,71.22 34.04,70.92 34.04,68.73 34.44,68.33 40.74,68.33 41.14,68.73 C15.1 C16.1 C14.1 C13.1 C12.1 R4.1 R7.1 39.37,80.94 38.99,81.03 38.99,83.57 38.73,83.82 37.22,83.82 37.02,83.62 37.02,81.66 36.82,81.46 R3.2 v1(36.22,80.74)
  L5_SIG w0.406: v1(35.42,79.14) 34.82,79.14 34.62,79.34 34.62,80.54 34.82,80.74 v1(36.22,80.74)
$3N6009: length 5.9
  TOP w0.254: U12.1 56.54,68.99 56.54,69.03 R100.2
  TOP w0.406: R100.2 R101.1 C7.1
$3N6012: length 3.3
  TOP w0.254: U12.6 53.21,72.99 52.92,73.28 R8.1
$4N2087: length 2.6
  TOP w0.14: R9.1 21.34,68.45 21.59,68.71 22.1,68.71 22.35,68.96 22.35,69.81 LED1.K
$5N38: length 4
  TOP w0.14: v2(27.3,40) U2.16
  BOTTOM w0.14: R73.2 R71.1 v2(27.3,40)
$5N56: length 5.5
  TOP w0.14: v2(23.49,30.48) 22.86,31.12 U2.8
  BOTTOM w0.14: R80.2 R72.1 v2(23.49,30.48)
$6N1711: length 16.6
  TOP w0.305: U1.L20 41.53,52.94 42.04,53.45 42.04,57.02 42.55,57.53 46.99,57.53 C29.1
  TOP w0.508: 51.43,55.63 51.18,55.75 51.18,57.18 50.67,57.69 C28.1 47.06,57.69 C29.1
$6N2071: length 7.1
  TOP w0.14: R13.1 43.56,51.74 v2(43.56,52.7)
  TOP w0.203: v1(39.42,52.54) U1.L18
  BOTTOM w0.508: v2(43.56,52.7) 43.56,53.14 43.16,53.54 40.02,53.54 39.42,52.94 v1(39.42,52.54)
$6N3598: length 12.9
  TOP w0.203: U1.L19 v1(40.22,52.54)
  TOP w0.508: 51.43,52.7 51.43,53.24 C30.1 47.05,53.24 C31.1 45.34,53.3 45.05,53.59 43.31,53.59 v2(42.42,52.7)
  L4_SIG w0.508: v2(42.42,52.7) 40.51,52.7 v1(40.22,52.54)
$6N4036: length 2.4
  TOP w0.508: R14.2 57.79,53.19 FER4.1
$6N5154: length 1.3
  BOTTOM w0.305: R15.1 C33.2
$6N5877: length 10
  TOP w0.305: U1.L7 U1.M7 v1(29.82,51.74)
  L4_SIG w0.305: v1(29.82,51.74) 28.52,53.04 24.32,53.04 v1(23.82,52.54)
  BOTTOM w0.305: R120.2 R119.2 v1(23.82,52.54)
$8N2576: length 11.7
  TOP w0.254: U9.7 43.84,30.99 v2(43.43,30.48) ; U9.24 43.84,35.81 43.43,35.81 43.18,36.07 v2(43.18,36.83)
  L5_SIG w0.635: v2(43.18,36.83) 43.43,36.45 v2(43.43,30.48)
  BOTTOM w0.305: 43.18,35.41 v2(43.18,36.83) R25.2
$8N2596: length 2.2
  TOP w0.14: R23.1 44.45,36.7 44.83,36.32 44.83,35.69 44.84,35.69 U9.22
$8N2617: length 2.9
  TOP w0.254: v2(42.16,32.89) 42.18,32.9 U9.5
  BOTTOM w0.305: R19.2 43.18,32.89 v2(42.16,32.89) 41.27,32.89 R18.1
$8N2622: length 10.1
  TOP w0.14: Y2.2 38.73,36.45 38.99,36.2 40.26,36.2 40.64,35.81 40.64,35.05 40.89,34.8 42.42,34.8 42.55,34.9 U9.1
$8N2623: length 9.6
  TOP w0.14: U9.2 42.67,34.41 42.42,34.42 40.64,34.42 40.26,34.8 40.26,35.56 40,35.81 38.99,35.81 38.73,35.56 Y2.1
$8N2657: length 2.5
  TOP w0.14: U9.14 47.37,32.9 47.38,32.9 v2(48.01,32.38) 48.41,32.38 R24.1
$8N3809: length 9.5
  TOP w0.254: v2(48.01,34.54) 48.01,34.16 47.75,33.9 U9.16 ; v2(45.34,36.83) 45.84,36.33 U9.20
  L5_SIG w0.635: v2(48.01,34.54) 48.01,35.34 47.61,35.74 45.74,35.74 45.34,36.14 v2(45.34,36.83)
  BOTTOM w0.254: 46.99,34.44 C144.1 46.99,34.54 v2(48.01,34.54) 48.89,34.54 R27.2
$8N3812: length 8.6
  TOP w0.254: U9.11 45.84,30.86 v2(46.1,30.48) ; v2(48.01,33.27) 47.63,33.4 47.62,33.41 U9.15
  L5_SIG w0.635: v2(46.1,30.48) 46.1,31.37 46.82,32.09 46.82,32.87 47.22,33.27 v2(48.01,33.27)
  BOTTOM w0.305: C143.1 46.99,32.87 47.4,33.27 v2(48.01,33.27) 48.49,33.27 R28.2
$8N3997: length 2.7
  TOP w0.14: R30.1 46.99,34.95 U9.18
$8N3999: length 2.5
  TOP w0.14: U9.10 45.33,30.99 v2(45.21,30.48)
  BOTTOM w0.14: v2(45.21,30.48) 45.21,31.75 45.22,31.75 R31.1
$8N4014: length 3.1
  TOP w0.14: R32.2 17.34,53.34 R34.1 R35.1
$8N4015: length 15.3
  TOP w0.14: R33.1 18.38,52.27 R34.2 17.15,51.56 16.76,51.18 13.84,51.18 13.33,50.67 Y1.2 13.33,45.09 C142.1
$8N4293: length 8.2
  TOP w0.14: R35.2 13.51,55.73 Y1.1 13.33,56.52 C141.1
$9N2124: length 4.1
  TOP w0.305: v2(12.7,94.87) 12.7,96.75 P2.5
  BOTTOM w0.305: v2(12.7,94.87) 12.19,94.36 10.95,94.36 FER2.1
$9N2147: length 1.9
  TOP w0.14: R83.1 LED7.K
$9N2148: length 1.9
  TOP w0.14: R84.1 LED8.K
$9N2149: length 15.6
  TOP w0.14: U10.22 12.8,85.61 12.66,85.47 11.81,85.47 v2(11.18,86.11) ; R84.2 v2(4.45,93.34)
  L5_SIG w0.14: v2(11.18,86.11) 10.16,87.12 10.16,88.52 9.27,89.41 9.27,92.2 8.76,92.71 5.08,92.71 v2(4.45,93.34)
$9N2150: length 13.3
  TOP w0.14: v2(12.19,86.11) 12.2,86.11 U10.21 ; R83.2 v2(6.35,93.34)
  L5_SIG w0.14: v2(12.19,86.11) 10.54,87.76 10.54,88.9 9.65,89.79 9.65,92.71 9.02,93.34 v2(6.35,93.34)
$9N2153: length 11.7
  TOP w0.133: P2.2 14.62,95.98 14.48,95.84 14.48,95.63 14.86,95.25 14.86,95 v1(15.11,94.74) 14.86,94.49 14.86,94.22 14.97,94.11 D2.1 ; U10.15 14.63,89.28 14.73,89.39 14.73,89.54 v1(14.48,89.79)
  BOTTOM w0.133: v1(15.11,94.74) 14.86,95 14.86,95.12 14.99,95.25 15.37,95.25 15.49,95.12 15.49,93.98 14.73,93.22 14.73,90.04 v1(14.48,89.79)
$9N2154: length 12.6
  TOP w0.133: D2.2 14.47,94.11 14.6,94.24 14.6,94.49 v1(14.35,94.74) 14.6,95 14.6,95.12 14.22,95.5 14.22,95.76 13.97,96.01 P2.3 ; v1(15.24,89.79) 14.99,89.54 14.99,89.42 15.12,89.28 U10.14
  BOTTOM w0.133: v1(15.24,89.79) 14.99,90.04 14.99,93.09 15.75,93.85 15.75,95.25 15.49,95.5 14.86,95.5 14.6,95.25 14.6,95 v1(14.35,94.74)
$9N2155: length 10.8
  TOP w0.254: v2(12.19,87.12) 12.2,87.11 U10.19
  BOTTOM w0.305: C194.1 v2(12.19,87.12) C193.1 13.08,87.19 13.08,87.88 13.72,88.52 16.76,88.52 17.15,88.9 FER1.2
$9N2158: length 3.4
  TOP w0.14: v2(11.18,88.14) 11.68,87.63 12.57,87.63 12.7,87.61 U10.18
  BOTTOM w0.14: v2(11.18,88.14) 11.18,89 R85.2
$9N3466: length 4
  TOP w0.14: R94.1 5.08,48.89
$10N4563: length 6.4
  TOP w0.14: R99.2 v2(5.71,10.67)
  L5_SIG w0.14: v1(4.45,14.1) 3.81,13.46 3.81,12.57 v2(5.71,10.67)
  BOTTOM w0.14: J3.95 4.44,14.1 v1(4.45,14.1)
$10N4564: length 7.5
  TOP w0.14: v1(0.89,14.35) 0.89,10.92 1.14,10.67 1.65,10.67 1.91,10.41 R98.2
  BOTTOM w0.14: v1(0.89,14.35) 1.27,14.73 J3.93
$10N4565: length 16.7
  TOP w0.14: R97.2 6.38,9.4 6.38,8.13 6,7.75 2.79,7.75 2.54,8 2.54,10.79 2.29,11.05 1.65,11.05 1.4,11.3 1.4,14.6 v1(0.89,15.11)
  BOTTOM w0.14: J3.91 2.03,15.37 v1(0.89,15.11)
$10N4566: length 9.6
  TOP w0.14: v1(0.89,15.88) 1.78,14.99 1.78,11.68 2.03,11.43 2.92,11.43 3.18,11.18 R96.2
  BOTTOM w0.14: v1(0.89,15.88) 1.4,16 J3.89
$10N4567: length 11.4
  TOP w0.14: v1(0.89,16.64) 2.16,15.37 2.16,12.06 2.41,11.81 4.06,11.81 4.32,11.56 4.32,10.01 R95.2
  BOTTOM w0.14: J3.87 0.89,16.64 v1(0.89,16.64)
$11N466: length 8.1
  TOP w0.14: R47.2 59.05,22.75 59.42,23.11 U4.3 59.56,23.88 60.07,23.88 60.32,24.13 60.32,27.56 60.07,27.81 60.07,28.9 U17.4
$11N467: length 1.9
  TOP w0.14: LED6.K 52.55,31.75 R46.1
$11N468: length 9.8
  TOP w0.14: SW2.2 55.63,35.73 55.09,35.18 R49.2 U17.2 v1(58.04,29.84)
$11N469: length 12
  TOP w0.14: U18.4 59.56,37.79 59.56,35.18 59.31,34.92 58.55,34.92 v1(58.04,35.43) ; U17.1 57.53,30.73 v1(58.04,30.73)
  L5_SIG w0.14: v1(58.04,35.43) 58.55,34.92 58.93,34.92 59.31,34.54 59.31,31.12 58.93,30.73 v1(58.04,30.73)
$11N1122: length 1.9
  TOP w0.14: R38.1 LED4.K
$11N1123: length 1.9
  TOP w0.14: R37.1 LED5.K
$11N1124: length 1.9
  TOP w0.14: R39.1 LED3.K
$11N1132: length 1.9
  TOP w0.14: R36.1 LED2.K
$11N1711: length 14.6
  TOP w0.14: U16.19 11.3,61.96 v2(10.79,61.98) ; v2(2.54,58.42) LED2.A
  L4_SIG w0.14: v2(2.54,58.42) 2.54,61.98 3.18,62.61 10.16,62.61 v2(10.79,61.98)
$11N1713: length 12
  TOP w0.14: v2(4.45,58.42) LED5.A ; v2(9.78,61.98) 10.41,62.61 U16.18
  L4_SIG w0.14: v2(9.78,61.98) 5.08,61.98 4.45,61.34 v2(4.45,58.42)
$11N1715: length 11.7
  TOP w0.14: v2(10.79,63.25) 10.81,63.26 U16.17 ; v2(6.99,58.42) 6.6,58.42 6.35,58.67 LED4.A
  L4_SIG w0.14: v2(6.99,58.42) 6.99,60.71 7.62,61.34 11.05,61.34 11.43,61.72 11.43,62.61 v2(10.79,63.25)
$11N2516: length 5.5
  TOP w0.14: U16.12 14.21,66.29 13.59,66.91 13.59,68.45 13.84,68.71 14.12,68.71 R41.1 R42.2
$11N2517: length 5.7
  TOP w0.14: R45.2 R44.1 12.42,68.71 12.95,68.71 13.21,68.45 13.21,66.68 13.56,66.32 U16.13
$11N2518: length 5.7
  TOP w0.14: R40.2 R43.1 16.13,68.71 15.49,68.71 15.11,68.33 15.11,67.18 14.86,66.93 U16.11
$12N6006: length 5.8
  TOP w0.254: 18.03,12.7 18.03,12.19 17.78,11.94 C163.2 ; 18.03,12.7 U15.19 ; 18.03,12.7 18.4,12.7 18.53,12.83 U15.20
  TOP w0.305: C163.2 19.02,11.25 R55.2 R54.1
$12N6225: length 3.7
  TOP w0.14: L3.1 44.83,18.03 44.83,16.64 ; 44.83,16.64 44.84,15.9 U14.6 ; 44.83,16.64 45.33,16.64 U14.5
$12N6230: length 4.3
  TOP w0.254: U14.12 45.33,12.52 C151.2
  TOP w0.305: 45.47,12.57 C151.2 ; 45.47,12.57 46.74,12.57 R52.1 ; 45.47,12.57 44.23,12.57 R63.2
$12N7569: length 9.2
  TOP w0.14: 16.98,20.88 C162.2 17.03,19 17.03,17.78 ; 16.98,20.88 15.62,20.32 ; 16.98,20.88 16.98,20.95 17.23,21.21 L4.1 16.98,20.88 ; 17.03,17.78 17.53,17.78 ; 17.03,17.78 U15.10 ; U15.8 18.03,17.78 17.53,17.78 ; 17.53,17.78 U15.9
$12N7589: length 1.9
  TOP w0.254: U15.7 18.53,19 C162.1
$12N7788: length 4
  TOP w0.254: U15.15 15.9,14.49 15.24,13.83 R58.2
  TOP w0.305: R58.2 R57.2 R121.1
$12N7803: length 11.8
  TOP w0.254: v2(17.15,12.06) 17.53,12.45 17.53,12.45 U15.18
  TOP w0.305: C168.1 v2(17.15,12.06) ; R122.1 v2(12.7,12.19) R121.2 R124.2 R123.1
  BOTTOM w0.305: v2(12.7,12.19) 13.33,11.56 16.64,11.56 v2(17.15,12.06)
$12N7837: length 2.8
  TOP w0.254: U15.17 17.03,13.06 R59.1
$12N8016: length 5.2
  TOP w0.254: U5.16 31.88,14.73 31.5,14.35 28.57,14.35 27.94,13.72 27.94,13.53 C173.2
$12N8049: length 3.3
  TOP w0.305: C174.1 31.12,10.57 30.73,10.19 R60.2
$12N8051: length 10.4
  TOP w0.254: C174.2 31.12,13.5 31.16,13.55 31.49,13.55 32.38,14.43 U5.17
  TOP w0.305: C185.2 31.12,13.53 31.13,13.52 ; C174.2 31.37,13.12 31.37,13.08 32.13,12.32 32.13,10.57 32.51,10.19 R65.1
$12N8198: length 8.4
  TOP w0.14: U5.8 31.88,19.49 L5.1 ; 32.88,18.8 U5.6 ; 32.88,18.8 32.88,18.99 32.38,19.49 ; 32.88,18.8 33.27,18.8 ; L5.1 32.38,19.49 ; L5.1 31.93,19.94 31.38,19.94 U5.9 ; U5.7 32.38,19.49
$12N8425: length 1.3
  TOP w0.305: R117.1 R66.2
$12N8479: length 11.3
  TOP w0.254: U5.18 32.88,13.37 C178.2 33.02,13.69
  TOP w0.305: 33.02,13.69 R64.2 R66.1 ; C218.1 37.46,11.15 R116.1 R65.2 34.16,11.15 33.91,11.4 33.91,12.57 33.4,13.08 33.31,13.08 C178.2
$12N8484: length 1.3
  TOP w0.305: R118.1 R52.2
$12N8942: length 3.5
  TOP w0.203: v1(15.62,14.99) 15.88,14.99 U15.14
  BOTTOM w0.305: v1(15.62,14.99) R29.2 13.84,15.65 13.84,15.57 R127.2
$13N133: length 37.9
  TOP w0.127: 36.07,99.44 v2(36.83,98.55)
  TOP w0.305: R110.1 v2(36.83,97.79) 39.83,99.31 D4.A 40,99.29 40.13,99.42 U19.5 43.99,99.42 43.99,98.76 ; v2(28.83,93.22) 28.98,93.6 P3.A9 28.98,94.62 29.23,94.87 P3.B4 ; 43.99,98.09 43.99,97.43 U19.8 ; 43.99,98.09 U19.9 43.99,98.76 ; 43.99,98.09 U19.7 ; P3.B9 31.73,94.91 31.98,94.66 P3.A4 31.98,93.6 v2(32.13,93.22) ; U19.6 43.99,98.76
  TOP w0.508: D5.K 28.18,91.44 C208.1 28.17,92.58 28.19,92.58 v2(28.83,93.22)
  BOTTOM w0.508: v2(36.83,98.55) v2(36.83,97.79) 36.83,93.47 36.07,92.71 33.91,92.71 33.4,93.22 v2(32.13,93.22) v2(28.83,93.22)
$13N256: length 3.2
  TOP w0.254: U21.13 48.64,92.73 48.89,92.48 v2(48.89,91.31)
  TOP w0.305: v2(48.89,91.31) R17.2
  BOTTOM w0.305: v2(48.89,91.31) R17.2
$13N259: length 2.1
  TOP w0.254: v2(47.62,91.31) 47.6,91.33 U21.12
  TOP w0.305: v2(47.62,91.31) R102.2
  BOTTOM w0.305: R102.2 v2(47.62,91.31)
$13N306: length 4.4
  TOP w0.254: U21.6 43.56,92.73 43.05,92.22 R115.1
  TOP w0.305: R115.1 R105.1
$13N308: length 2
  TOP w0.254: U21.7 45.11,91.95 44.7,91.95 44.32,91.57 R112.1
$13N309: length 1.4
  TOP w0.254: R113.1 45.6,90.65 U21.8
$13N457: length 16
  TOP w0.305: R108.1 56.52,99.03 56.13,99.41 R107.1 55.24,99.42 U20.4 53.34,99.42 53.34,100.33 53.09,100.58 47.88,100.58 47.62,100.33 R106.2 47.5,99.42 U19.4
$13N525: length 1.3
  TOP w0.305: R108.2 56.49,94.8 C212.2
$13N528: length 11.2
  TOP w0.254: U21.16 49.03,94.23 v2(49.53,93.73)
  TOP w0.305: v2(55.24,97.54) R107.2
  L4_SIG w0.305: v2(49.53,93.73) 50.42,93.73 51.05,94.36 51.05,96.9 51.69,97.54 v2(55.24,97.54)
$13N538: length 7.7
  TOP w0.14: R114.1 50.16,95.5 49.66,96.01 47.6,96.01 U21.19
$13N593: length 7.7
  TOP w0.508: C213.1 36.83,92.84 R109.1
  TOP w0.889: D4.K 39.77,94.94 R110.2 C213.1
$13N599: length 15.4
  TOP w0.254: U21.18 49.02,95.23 v2(49.53,94.87)
  TOP w0.305: v2(40.89,92.84) R109.2
  L4_SIG w0.305: v2(49.53,94.87) 47.12,97.28 42.29,97.28 40.89,95.89 v2(40.89,92.84)
$13N626: length 12
  TOP w0.254: v2(46.61,90.93) 46.11,91.44 U21.9
  TOP w0.305: R111.2 v2(53.98,93.98)
  L4_SIG w0.305: v2(53.98,93.98) 53.98,92.58 53.47,92.08 46.99,92.08 46.61,91.69 v2(46.61,90.93)

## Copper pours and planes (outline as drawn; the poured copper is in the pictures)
3V on TOP (solid shape): 13.84,25.91 9.4,25.91 9.4,28.7 13.84,28.7
3V on TOP (solid shape): 52.83,71.25 52.94,71.13 52.94,68.27 51.93,68.27 51.93,72.64 52.83,72.64
3V on L2_PWR (solid shape): outline of 22164 points within 0.66,20.35 59.03,100.94
GND on TOP (solid shape): 62.04,71.88 59.84,71.88 59.84,78.11 62.04,78.11
GND on TOP (solid shape): 62.04,66.93 59.84,66.93 59.84,71.5 62.04,71.5
GND on TOP (solid shape): 42.16,17.02 44.5,16.08 44.5,15.62 39.12,15.62 39.12,20.07 42.16,20.07
GND on TOP (solid shape): 52.45,16.64 51.82,16 46.74,16 46.28,15.57 45.67,15.57 45.67,16.08 48.01,17.15 48.01,20.32 50.29,20.32 50.67,20.7 50.67,27.69 52.45,27.69
GND on TOP (solid shape): outline of 231 points within 27.24,8.45 38.67,16.24
GND on TOP (solid shape): outline of 636 points within 5.48,0.7 22.93,10.34
GND on TOP (solid shape): outline of 2171 points within 13.76,53.68 32.68,71.8
GND on TOP (solid shape): outline of 26383 points within 0.7,0.7 62.8,100.9
GND on BOTTOM (solid shape): outline of 299 points within 20.66,40.77 24.51,44.49
GND on BOTTOM (solid shape): outline of 507 points within 31.96,59.68 40.23,66.11
GND on BOTTOM (solid shape): outline of 874 points within 9.99,29.67 18.46,60.46
GND on BOTTOM (solid shape): outline of 1455 points within 14.18,35.95 25.88,57.82
GND on BOTTOM (solid shape): outline of 23953 points within 0.7,0.7 62.8,100.9
GND on L2_PWR (solid shape): outline of 890 points within 51.59,65.43 62.84,100.94
GND on L3_GND (solid shape): outline of 236 points within 28.28,9.87 38.07,16.48
GND on L3_GND (solid shape): outline of 42723 points within 0.66,0.66 62.84,100.94
GND on L6_GND (solid shape): outline of 42983 points within 0.66,0.66 62.84,100.94
GND on L7_PWR (solid shape): outline of 893 points within 30.16,65.21 62.8,88.2
VBUS_TYPEC on TOP (solid shape): 8.76,16.38 4.32,16.38 4.32,19.05 6.22,19.05 7.24,20.07 8.76,20.07
VBUS_TYPEC on TOP (solid shape): 52.58,99.21 52.83,98.96 54.08,98.96 54.08,97.23 52.83,97.23 52.58,96.98 52.58,96.65 48.26,96.65 48.26,96.98 48.01,97.23 45.47,97.23 45.47,98.96 48.01,98.96 48.26,99.21 48.26,100.2 52.58,100.2
VBUS_TYPEC on L7_PWR (solid shape): outline of 8458 points within 0.66,16.54 62.84,100.94
VDD_CONNECTOR on TOP (solid shape): 3.94,13.97 4.32,13.59 5.71,13.59 5.71,12.57 2.92,12.57 2.54,12.95 2.54,15.62 2.16,16 2.16,20.07 3.94,20.07
VDD_CONNECTOR on BOTTOM (solid shape): 5.71,12.7 4.06,12.7 4.06,13.59 5.71,13.59
VDD_EXT on TOP (solid shape): 10.67,5.71 7.37,5.71 7.37,7.62 10.67,7.62
VDD_EXT on TOP (solid shape): 29.72,15.75 26.42,15.75 26.42,18.54 29.72,18.54
VDD_EXT on TOP (solid shape): 37.85,15.62 36.83,15.62 36.2,16.26 34.67,16.26 34.42,16.51 34.42,18.29 37.85,18.29
VDD_EXT on TOP (solid shape): 59.18,61.21 57.15,61.21 56.77,60.83 56.77,59.44 52.96,59.44 52.96,62.61 53.85,63.5 59.18,63.5
VDD_EXT on TOP (solid shape): 21.46,20.19 19.94,20.19 19.94,23.49 19.56,23.88 14.22,23.88 14.22,25.27 15.11,25.27 15.37,25.53 15.37,29.34 15.75,29.72 21.46,29.72
VDD_EXT on TOP (solid shape): 51.31,9.53 50.42,8.64 40.64,8.64 39.12,10.16 39.12,15.29 44.48,15.29 44.48,14.05 42.55,14.05 42.29,13.79 42.29,12.19 42.55,11.94 43.43,11.94 43.43,10.54 44.2,9.78 49.15,9.78 49.53,10.16 49.53,13.21 49.28,13.46 49.28,14.1 48.62,14.73 46.86,14.73 46.56,15.04 45.95,15.04 45.95,15.34 46.47,15.34 46.91,15.75 51.31,15.75
VDD_EXT on L2_PWR (solid shape): outline of 9809 points within 16.85,41.62 48.87,66.27
VDD_EXT on L2_PWR (solid shape): outline of 11883 points within 4.15,0.66 62.84,65.06
VDD_EXT on L4_SIG (solid shape): 10.67,5.71 7.37,5.71 7.37,7.62 10.67,7.62
VDD_EXT on L4_SIG (solid shape): outline of 1859 points within 2.44,5.74 27.97,44.04
VDD_INPUT on TOP (solid shape): 25.91,16.36 19.69,16.36 19.69,19.18 21.84,19.18 22.48,19.81 25.91,19.81
VDD_INPUT on TOP (solid shape): 13.08,22.61 13.08,19.56 13.46,19.18 15.88,19.18 15.88,16.36 9.91,16.36 9.91,19.94 9.53,20.32 7.11,20.32 6.1,19.3 4.7,19.3 4.7,22.99 12.7,22.99
VDD_INPUT on BOTTOM (solid shape): 14.22,20.07 25.65,20.07 25.65,17.53 9.65,17.53 9.65,21.21 13.08,21.21
VDD_INT on TOP (solid shape): 35.94,21.97 28.32,21.97 28.32,28.32 35.94,28.32
VDD_INT on BOTTOM (solid shape): 35.94,21.97 28.32,21.97 28.32,25.02 35.94,25.02
VDD_INT on L2_PWR (solid shape): outline of 11253 points within 0.66,6.05 38.96,66.27
VDD_VREF_EXT on TOP (solid shape): 62.23,52.83 60.71,52.83 60.71,54.61 59.69,55.63 59.69,58.55 59.05,59.18 58.04,59.18 58.04,60.45 59.05,60.45 59.69,61.09 59.69,62.74 62.23,62.74
VDD_VREF_EXT on L7_PWR (solid shape): outline of 10560 points within 16.85,43.52 62.84,60.17
1_8V on L7_PWR (solid shape): outline of 6132 points within 16.85,29.55 62.84,54.97
1_35V on TOP (solid shape): 49.4,20.57 42.55,20.57 42.55,27.69 49.4,27.69
1_35V on TOP (solid shape): 59.44,66.93 57.24,66.93 57.24,71.63 59.44,71.63
1_35V on L7_PWR (solid shape): outline of 33884 points within 0.66,0.66 62.84,88.24
DMC0_VREF on TOP (solid shape): 49.78,81.03 49.78,65.02 44.2,65.02 44.2,79.63 43.94,80.01 42.04,80.01 41.78,80.26 41.78,81.41 42.04,81.66 49.15,81.66
DMC0_VREF on BOTTOM (solid shape): 47.29,56.21 44.32,56.21 44.32,57.02 47.29,57.02
DMC0_VREF on L4_SIG (solid shape): 45.34,65.02 44.96,64.64 44.96,57.15 45.21,56.9 45.72,56.9 45.72,56.13 44.58,56.13 44.2,56.52 44.2,65.79 44.45,66.04 45.34,66.04
VTT on TOP (solid shape): 59.44,71.87 57.28,71.89 57.28,73.53 56.39,73.53 56.39,74.42 54.86,74.42 54.86,78.49 52.7,78.49 52.7,80.01 59.44,80.01
VTT on BOTTOM (solid shape): 51.82,87.88 51.82,80.65 52.45,80.01 59.56,80.01 59.56,71.88 56.01,71.88 56.01,73.66 55.63,74.04 52.07,74.04 51.69,73.66 51.69,66.42 51.43,66.17 43.81,66.17 43.43,65.79 40.77,65.79 40.64,65.99 32.82,65.99 32.82,67.34 38.1,67.34 38.23,67.47 38.23,68.33 38.48,68.58 40.13,68.58 40.39,68.83 40.39,70.74 40.64,70.99 43.43,70.99 43.69,71.25 43.69,71.5 44.83,71.5 44.83,72.64 43.69,72.64 43.69,74.8 44.83,74.8 44.83,75.82 43.69,75.82 43.69,77.98 44.83,77.98 44.83,78.99 43.69,78.99 43.69,81.15 44.83,81.15 44.83,82.8 42.93,82.8 41.91,83.82 41.91,84.2 41.4,84.71 40.36,84.71 39.09,86 33.4,86 33.4,88.27 51.43,88.27
$3N3334 on TOP (solid shape): 39.62,84.07 39.62,82.04 40,81.66 41.27,81.66 41.53,81.41 41.53,67.95 40.89,67.31 34.16,67.31 33.53,67.95 33.53,70.48 33.15,70.87 31.75,70.87 31.75,72.26 34.42,72.26 35.05,71.63 35.05,69.34 35.43,68.96 39.5,68.96 39.88,69.34 39.88,80.14 39.5,80.52 38.86,80.52 38.48,80.9 38.48,83.31 38.23,83.57 37.54,83.57 37.29,83.31 37.29,80.72 36.96,80.39 35.81,80.39 35.81,81.79 36.7,81.79 36.7,84.07 37.08,84.46 39.24,84.46
$12N6225 on TOP (solid shape): 47.37,17.15 45.44,16.23 45.44,15.88 44.73,15.88 44.73,16.23 42.55,17.15 42.55,18.54 47.37,18.54
$12N7569 on TOP (solid shape): 18.8,20.19 18.03,20.19 17.65,19.81 17.65,18.41 18.16,17.91 18.16,16.84 16.89,16.84 16.89,17.53 16.26,18.16 16.26,19.81 15.88,20.19 14.22,20.19 14.22,21.84 18.8,21.84
$12N8198 on TOP (solid shape): 33.4,18.67 33.02,18.29 31.24,18.29 30.86,18.67 30.86,20.57 33.4,20.57
